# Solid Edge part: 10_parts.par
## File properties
Author: edge
Template: jis part.par
Last saved by: edge
Revision: 5
Application: Solid Edge
文書内容のタイプ: 0
Accuracy: 0.990
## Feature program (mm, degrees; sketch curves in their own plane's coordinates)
sketch for "unnamed Protrusion 1" plane through (10.8674, 10.8674, 0) normal (0, 0, 1) x-axis (1, 0, 0)
  circle centre (-10.8674, -10.8674) radius 15
extrude "unnamed Protrusion 1" add finite 8 along +normal
sketch for "ExtrudedProtrusion_4" plane through (0, 10.8674, 10.8674) normal (1, 0, 0) x-axis (0, 1, 0)
  line (-10.8674, -10.8674) -> (-32.6836, -10.8674)
  line (-32.6836, -10.8674) -> (-53.992, -28.7473)
  line (-53.992, -28.7473) -> (-57.8487, -24.151)
  line (-57.8487, -24.151) -> (-34.8674, -4.8674)
  line (-34.8674, -4.8674) -> (-10.8674, -4.8674)
  line (-10.8674, -4.8674) -> (-10.8674, -10.8674)
  dimension (linear) = 53.992
  dimension (linear) = 34.8674
  dimension (linear) = 57.8487
  dimension (linear) = 10.8674
extrude "ExtrudedProtrusion_4" add finite 20 symmetric
fillet "Round_1" radius 10
fillet "Round_2" radius 3
fillet "Round_3" radius 3
sketch for "unnamed Cutout 1" plane through (0, -35.9089, -3.9927) normal (0, -0.642788, 0.766044) x-axis (0, 0.766044, 0.642788)
  line (0, 0) -> (0, 0)
  line (-4.454, 5) -> (5.546, 5)
  line (5.546, -5) -> (-4.454, -5)
extrude "unnamed Cutout 1" cut through along -normal
sketch for "Hole_1" plane through (0, 0, 8) normal (0, 0, 1) x-axis (0, 1, 0)
  hole centre (0, 0) bore radius 10
hole "Hole_1" diameter 20 through
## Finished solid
Body 1: solid body, 18 faces, 45 edges, 28 vertices.
  Faces by surface: cylinder 9, plane 9
  Edges by curve: line 26, circle 19
Bounding box of the edges (mm): 30.000 x 61.981 x 25.880, from (-15, -46.9813, -17.8799) to (15, 15, 8).
Cylindrical faces by radius (mm): R3 x4, R5 x2, R10 x2, R15 x1
Planar faces by outward normal: +x 2, +z 2, -x 2, -z 1, oblique 2
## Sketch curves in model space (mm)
line (-5, -31.6604, -0.4279) -> (5, -31.6604, -0.4279)
line (5, -39.3209, -6.8558) -> (-5, -39.3209, -6.8558)
arc centre (0, -31.6604, -0.4279) radius 5 from (-5, -31.6604, -0.4279) through (0.1482, -27.8319, 2.7847) to (5, -31.6604, -0.4279)
line (5, -31.6604, -0.4279) -> (5, -39.3209, -6.8558)
arc centre (0, -39.3209, -6.8558) radius 5 from (5, -39.3209, -6.8558) through (-0.1482, -43.1494, -10.0683) to (-5, -39.3209, -6.8558)
line (-5, -39.3209, -6.8558) -> (-5, -31.6604, -0.4279)
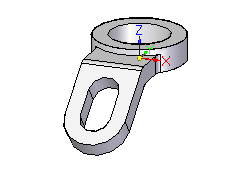
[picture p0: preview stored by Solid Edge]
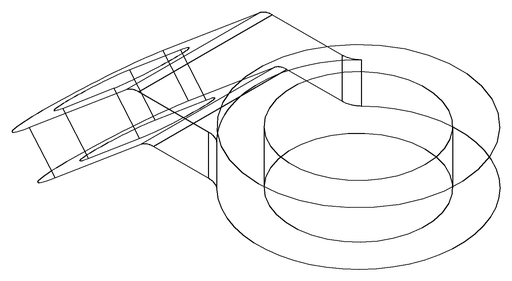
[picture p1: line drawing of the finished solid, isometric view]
